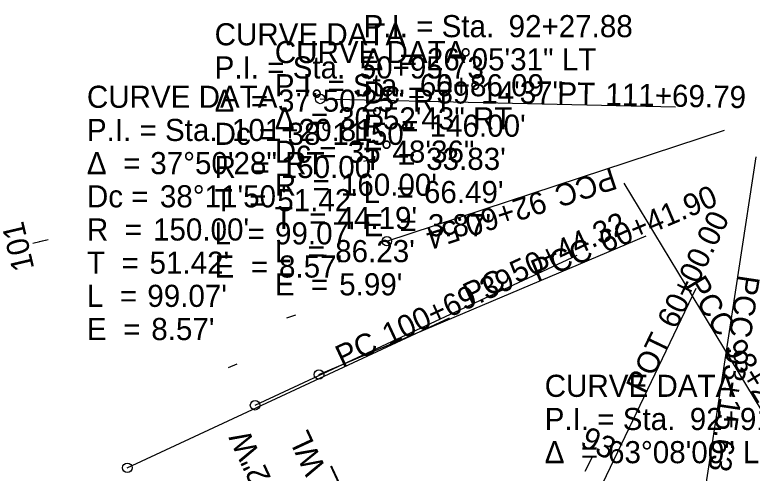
# Model space of a CAD drawing. Extents: x 1564517 to 1565226, y 635740 to 637455.
# Drawn here: x 1564729.9 to 1564823.3, y 636572.5 to 636630.6 of the extents above; entities that cross this region are included whole.
import ezdxf

# ---------------------------------------------------------------- set-up
doc = ezdxf.new("R2010")
doc.units = 0
for name, color, linetype in [('GE_P_Alignment_1000_Cardinal_Points', 7, 'Continuous'), ('GE_P_Alignment_500_Cardinal_Points', 7, 'Continuous'), ('GK_Drainage_Nodes', 7, 'Continuous'), ('SC_Scratch10', 7, 'Continuous'), ('TX_P_1000', 7, 'Continuous'), ('UT_P_Water', 7, 'Continuous'), ('UT_P_Water_Cells', 7, 'Continuous'), ('UT_X_Sanitary_Pressure_Line', 7, 'Continuous'), ('UT_X_Water_Cells', 7, 'Continuous')]:
    doc.layers.add(name, color=color, linetype=linetype)

msp = doc.modelspace()

# ---------------------------------------------------------------- linework, layer by layer
at = {"layer": 'GE_P_Alignment_1000_Cardinal_Points'}
msp.add_line((1564768.625, 636619.918), (1564813.615, 636618.935), dxfattribs=at)
msp.add_circle((1564768.625, 636619.918), 0.6, dxfattribs=at)
at = {"layer": 'GE_P_Alignment_500_Cardinal_Points'}
msp.add_line((1564768.625, 636619.918), (1564813.615, 636618.935), dxfattribs=at)
msp.add_circle((1564768.625, 636619.918), 0.6, dxfattribs=at)
at = {"layer": 'TX_P_1000'}
for p, q in [((1564768.459, 636585.03), (1564809.887, 636602.6)), ((1564760.364, 636581.139), (1564801.162, 636600.127)), ((1564796.769, 636555.382), (1564816.233, 636595.955))]:
    msp.add_line(p, q, dxfattribs=at)
at = {"layer": 'UT_P_Water_Cells'}
for p, q in [((1564777.06, 636601.911), (1564819.81, 636615.963)), ((1564817.022, 636568.096), (1564823.806, 636612.582)), ((1564830.4, 636570.761), (1564807.083, 636609.25)), ((1564734.189, 636602.095), (1564733.021, 636601.82)), ((1564768.459, 636585.03), (1564809.887, 636602.6)), ((1564760.364, 636581.139), (1564801.162, 636600.127)), ((1564796.769, 636555.382), (1564816.233, 636595.955)), ((1564744.193, 636573.226), (1564784.991, 636592.214)), ((1564802.186, 636572.809), (1564802.723, 636573.883))]:
    msp.add_line(p, q, dxfattribs=at)
for centre in [(1564777.06, 636601.911), (1564768.459, 636585.03), (1564760.364, 636581.139), (1564744.193, 636573.226)]:
    msp.add_circle(centre, 0.6, dxfattribs=at)
at = {"layer": 'UT_X_Sanitary_Pressure_Line'}
for p, q in [((1564777.06, 636601.911), (1564819.81, 636615.963)), ((1564817.022, 636568.096), (1564823.806, 636612.582)), ((1564830.4, 636570.761), (1564807.083, 636609.25)), ((1564768.459, 636585.03), (1564809.887, 636602.6)), ((1564760.364, 636581.139), (1564801.162, 636600.127)), ((1564796.769, 636555.382), (1564816.233, 636595.955)), ((1564744.193, 636573.226), (1564784.991, 636592.214))]:
    msp.add_line(p, q, dxfattribs=at)
for centre in [(1564777.06, 636601.911), (1564768.459, 636585.03), (1564760.364, 636581.139), (1564744.193, 636573.226)]:
    msp.add_circle(centre, 0.6, dxfattribs=at)
at = {"layer": 'UT_X_Water_Cells'}
for p, q in [((1564774.134, 636612.03), (1564775.298, 636612.321)), ((1564734.189, 636602.095), (1564732.242, 636601.636)), ((1564769.354, 636600.155), (1564768.16, 636600.041)), ((1564765.486, 636592.565), (1564764.359, 636592.153)), ((1564758.065, 636586.333), (1564756.959, 636585.868)), ((1564802.186, 636572.809), (1564803.081, 636574.598))]:
    msp.add_line(p, q, dxfattribs=at)

# ---------------------------------------------------------------- texts
at = {"layer": 'GE_P_Alignment_1000_Cardinal_Points'}
for s, p in [('PT', (1564798.618, 636619.263)), ('111+69.79', (1564804.703, 636619.13))]:
    msp.add_text(s, height=2.8, rotation=358.74802, dxfattribs=at).set_placement(p)
at = {"layer": 'GE_P_Alignment_500_Cardinal_Points'}
for s, p in [('PT', (1564798.618, 636619.263)), ('111+69.79', (1564804.703, 636619.13))]:
    msp.add_text(s, height=2.8, rotation=358.74802, dxfattribs=at).set_placement(p)
at = {"layer": 'GK_Drainage_Nodes'}
for s, p in [('P.I. = Sta. ', (1564774.102, 636627.735)), ('92+27.88', (1564792.47, 636627.735)), ('CURVE DATA', (1564755.248, 636626.706)), ('CURVE DATA', (1564762.868, 636624.456)), ('Δ  = ', (1564774.102, 636623.535)), ('26°05\'31" LT', (1564782.124, 636623.535)), ('P.I. = Sta. ', (1564755.248, 636622.506)), ('50+95.73', (1564773.616, 636622.506)), ('P.I. = Sta. ', (1564762.868, 636620.256)), ('60+86.09', (1564781.236, 636620.256)), ('Dc = ', (1564774.102, 636619.335)), ('39°14\'37"', (1564783.34, 636619.335)), ('CURVE DATA', (1564739.077, 636618.794)), ('Δ  = ', (1564755.248, 636618.306)), ('37°50\'25" RT', (1564763.27, 636618.306)), ('Δ  = ', (1564762.868, 636616.056)), ('30°52\'43" RT', (1564770.89, 636616.056)), ('R  = ', (1564774.102, 636615.135)), ("146.00'", (1564782.47, 636615.135)), ('P.I. = Sta. ', (1564739.077, 636614.594)), ('101+20.81', (1564757.445, 636614.594)), ('Dc = ', (1564755.248, 636614.106)), ('38°11\'50"', (1564764.486, 636614.106)), ('Dc = ', (1564762.868, 636611.856)), ('35°48\'36"', (1564772.106, 636611.856)), ('T  = ', (1564774.102, 636610.935)), ("33.83'", (1564782.034, 636610.935)), ('Δ  = ', (1564739.077, 636610.394)), ('37°50\'28" RT', (1564747.099, 636610.394)), ('R  = ', (1564755.248, 636609.906)), ("150.00'", (1564763.616, 636609.906)), ('R  = ', (1564762.868, 636607.656)), ("160.00'", (1564771.236, 636607.656)), ('L  = ', (1564774.102, 636606.735)), ("66.49'", (1564781.748, 636606.735)), ('Dc = ', (1564739.077, 636606.194)), ('38°11\'50"', (1564748.315, 636606.194)), ('T  = ', (1564755.248, 636605.706)), ("51.42'", (1564763.18, 636605.706)), ('T  = ', (1564762.868, 636603.456)), ("44.19'", (1564770.8, 636603.456)), ("150.00'", (1564747.445, 636601.994)), ('E  = ', (1564774.102, 636602.535)), ("3.87'", (1564782.254, 636602.535)), ('R  = ', (1564739.077, 636601.994)), ('L  = ', (1564755.248, 636601.506)), ("99.07'", (1564762.894, 636601.506)), ('L  = ', (1564762.868, 636599.256)), ("86.23'", (1564770.514, 636599.256)), ('T  = ', (1564739.077, 636597.794)), ("51.42'", (1564747.009, 636597.794)), ('E  = ', (1564755.248, 636597.306)), ("8.57'", (1564763.4, 636597.306)), ('E  = ', (1564762.868, 636595.056)), ("5.99'", (1564771.02, 636595.056)), ("99.07'", (1564746.723, 636593.594)), ('L  = ', (1564739.077, 636593.594)), ('E  = ', (1564739.077, 636589.394)), ("8.57'", (1564747.229, 636589.394)), ('CURVE DATA', (1564797.041, 636582.204)), ('P.I. = Sta. ', (1564797.041, 636578.004)), ('92+91.26', (1564815.409, 636578.004)), ('Δ  = ', (1564797.041, 636573.804)), ('63°08\'00" LT', (1564805.063, 636573.804))]:
    msp.add_text(s, height=2.8, dxfattribs=at).set_placement(p)
for s, p in [('CLP_WL', (1564773.341, 636564.634)), ('N24°57\'32"W', (1564768.906, 636558.046))]:
    msp.add_text(s, height=2.8, rotation=114.95884, dxfattribs=at).set_placement(p)
at = {"layer": 'SC_Scratch10'}
for s, p in [('P.I. = Sta. ', (1564774.102, 636627.735)), ('92+27.88', (1564792.47, 636627.735)), ('CURVE DATA', (1564755.248, 636626.706)), ('CURVE DATA', (1564762.868, 636624.456)), ('Δ  = ', (1564774.102, 636623.535)), ('26°05\'31" LT', (1564782.124, 636623.535)), ('P.I. = Sta. ', (1564755.248, 636622.506)), ('50+95.73', (1564773.616, 636622.506)), ('P.I. = Sta. ', (1564762.868, 636620.256)), ('60+86.09', (1564781.236, 636620.256)), ('Dc = ', (1564774.102, 636619.335)), ('39°14\'37"', (1564783.34, 636619.335)), ('CURVE DATA', (1564739.077, 636618.794)), ('Δ  = ', (1564755.248, 636618.306)), ('37°50\'25" RT', (1564763.27, 636618.306)), ('Δ  = ', (1564762.868, 636616.056)), ('30°52\'43" RT', (1564770.89, 636616.056)), ('R  = ', (1564774.102, 636615.135)), ("146.00'", (1564782.47, 636615.135)), ('P.I. = Sta. ', (1564739.077, 636614.594)), ('101+20.81', (1564757.445, 636614.594)), ('Dc = ', (1564755.248, 636614.106)), ('38°11\'50"', (1564764.486, 636614.106)), ('Dc = ', (1564762.868, 636611.856)), ('35°48\'36"', (1564772.106, 636611.856)), ('T  = ', (1564774.102, 636610.935)), ("33.83'", (1564782.034, 636610.935)), ('Δ  = ', (1564739.077, 636610.394)), ('37°50\'28" RT', (1564747.099, 636610.394)), ('R  = ', (1564755.248, 636609.906)), ("150.00'", (1564763.616, 636609.906)), ('R  = ', (1564762.868, 636607.656)), ("160.00'", (1564771.236, 636607.656)), ('L  = ', (1564774.102, 636606.735)), ("66.49'", (1564781.748, 636606.735)), ('Dc = ', (1564739.077, 636606.194)), ('38°11\'50"', (1564748.315, 636606.194)), ('T  = ', (1564755.248, 636605.706)), ("51.42'", (1564763.18, 636605.706)), ('T  = ', (1564762.868, 636603.456)), ("44.19'", (1564770.8, 636603.456)), ("150.00'", (1564747.445, 636601.994)), ('E  = ', (1564774.102, 636602.535)), ("3.87'", (1564782.254, 636602.535)), ('R  = ', (1564739.077, 636601.994)), ('L  = ', (1564755.248, 636601.506)), ("99.07'", (1564762.894, 636601.506)), ('L  = ', (1564762.868, 636599.256)), ("86.23'", (1564770.514, 636599.256)), ('T  = ', (1564739.077, 636597.794)), ("51.42'", (1564747.009, 636597.794)), ('E  = ', (1564755.248, 636597.306)), ("8.57'", (1564763.4, 636597.306)), ('E  = ', (1564762.868, 636595.056)), ("5.99'", (1564771.02, 636595.056)), ("99.07'", (1564746.723, 636593.594)), ('L  = ', (1564739.077, 636593.594)), ('E  = ', (1564739.077, 636589.394)), ("8.57'", (1564747.229, 636589.394)), ('CURVE DATA', (1564797.041, 636582.204)), ('P.I. = Sta. ', (1564797.041, 636578.004)), ('92+91.26', (1564815.409, 636578.004)), ('Δ  = ', (1564797.041, 636573.804)), ('63°08\'00" LT', (1564805.063, 636573.804))]:
    msp.add_text(s, height=2.8, dxfattribs=at).set_placement(p)
for s, p in [('CLP_WL', (1564773.341, 636564.634)), ('N24°57\'32"W', (1564768.906, 636558.046))]:
    msp.add_text(s, height=2.8, rotation=114.95884, dxfattribs=at).set_placement(p)
at = {"layer": 'UT_P_Water'}
for s, p in [('P.I. = Sta. ', (1564774.102, 636627.735)), ('92+27.88', (1564792.47, 636627.735)), ('CURVE DATA', (1564755.248, 636626.706)), ('CURVE DATA', (1564762.868, 636624.456)), ('Δ  = ', (1564774.102, 636623.535)), ('26°05\'31" LT', (1564782.124, 636623.535)), ('P.I. = Sta. ', (1564755.248, 636622.506)), ('50+95.73', (1564773.616, 636622.506)), ('P.I. = Sta. ', (1564762.868, 636620.256)), ('60+86.09', (1564781.236, 636620.256)), ('Dc = ', (1564774.102, 636619.335)), ('39°14\'37"', (1564783.34, 636619.335)), ('CURVE DATA', (1564739.077, 636618.794)), ('Δ  = ', (1564755.248, 636618.306)), ('37°50\'25" RT', (1564763.27, 636618.306)), ('Δ  = ', (1564762.868, 636616.056)), ('30°52\'43" RT', (1564770.89, 636616.056)), ('R  = ', (1564774.102, 636615.135)), ("146.00'", (1564782.47, 636615.135)), ('P.I. = Sta. ', (1564739.077, 636614.594)), ('101+20.81', (1564757.445, 636614.594)), ('Dc = ', (1564755.248, 636614.106)), ('38°11\'50"', (1564764.486, 636614.106)), ('Dc = ', (1564762.868, 636611.856)), ('35°48\'36"', (1564772.106, 636611.856)), ('T  = ', (1564774.102, 636610.935)), ("33.83'", (1564782.034, 636610.935)), ('Δ  = ', (1564739.077, 636610.394)), ('37°50\'28" RT', (1564747.099, 636610.394)), ('R  = ', (1564755.248, 636609.906)), ("150.00'", (1564763.616, 636609.906)), ('R  = ', (1564762.868, 636607.656)), ("160.00'", (1564771.236, 636607.656)), ('L  = ', (1564774.102, 636606.735)), ("66.49'", (1564781.748, 636606.735)), ('Dc = ', (1564739.077, 636606.194)), ('38°11\'50"', (1564748.315, 636606.194)), ('T  = ', (1564755.248, 636605.706)), ("51.42'", (1564763.18, 636605.706)), ('T  = ', (1564762.868, 636603.456)), ("44.19'", (1564770.8, 636603.456)), ("150.00'", (1564747.445, 636601.994)), ('E  = ', (1564774.102, 636602.535)), ("3.87'", (1564782.254, 636602.535)), ('R  = ', (1564739.077, 636601.994)), ('L  = ', (1564755.248, 636601.506)), ("99.07'", (1564762.894, 636601.506)), ('L  = ', (1564762.868, 636599.256)), ("86.23'", (1564770.514, 636599.256)), ('T  = ', (1564739.077, 636597.794)), ("51.42'", (1564747.009, 636597.794)), ('E  = ', (1564755.248, 636597.306)), ("8.57'", (1564763.4, 636597.306)), ('E  = ', (1564762.868, 636595.056)), ("5.99'", (1564771.02, 636595.056)), ("99.07'", (1564746.723, 636593.594)), ('L  = ', (1564739.077, 636593.594)), ('E  = ', (1564739.077, 636589.394)), ("8.57'", (1564747.229, 636589.394)), ('CURVE DATA', (1564797.041, 636582.204)), ('P.I. = Sta. ', (1564797.041, 636578.004)), ('92+91.26', (1564815.409, 636578.004)), ('Δ  = ', (1564797.041, 636573.804)), ('63°08\'00" LT', (1564805.063, 636573.804))]:
    msp.add_text(s, height=2.8, dxfattribs=at).set_placement(p)
for s, p in [('CLP_WL', (1564773.341, 636564.634)), ('N24°57\'32"W', (1564768.906, 636558.046))]:
    msp.add_text(s, height=2.8, rotation=114.95884, dxfattribs=at).set_placement(p)
at = {"layer": 'UT_P_Water_Cells'}
for s, rotation, p in [('PCC', 198.19555, (1564805.56, 636611.279)), ('60+41.90', 22.98217, (1564804.684, 636600.393)), ('92+60.54', 198.19555, (1564796.68, 636608.36)), ('50+44.32', 24.95884, (1564793.476, 636596.55)), ('60+00.00', 64.37239, (1564813.694, 636590.662)), ('PCC', 22.98217, (1564796.078, 636596.744)), ('100+69.39', 24.95884, (1564777.304, 636588.637)), ('PC', 24.95884, (1564787.563, 636593.798)), ('PCC', 301.20754, (1564814.855, 636596.42)), ('PCC', 261.32885, (1564821.544, 636597.753)), ('PC', 24.95884, (1564771.391, 636585.885)), ('POT', 64.37239, (1564809.745, 636582.431)), ('93+29.55', 301.20754, (1564819.699, 636588.425)), ('93+15.63', 261.32885, (1564820.135, 636588.512))]:
    msp.add_text(s, height=2.8, rotation=rotation, dxfattribs=at).set_placement(p)
at = {"layer": 'UT_X_Sanitary_Pressure_Line'}
for s, rotation, p in [('PCC', 198.19555, (1564805.56, 636611.279)), ('60+41.90', 22.98217, (1564804.684, 636600.393)), ('92+60.54', 198.19555, (1564796.68, 636608.36)), ('50+44.32', 24.95884, (1564793.476, 636596.55)), ('60+00.00', 64.37239, (1564813.694, 636590.662)), ('PCC', 22.98217, (1564796.078, 636596.744)), ('100+69.39', 24.95884, (1564777.304, 636588.637)), ('PC', 24.95884, (1564787.563, 636593.798)), ('PCC', 301.20754, (1564814.855, 636596.42)), ('PCC', 261.32885, (1564821.544, 636597.753)), ('PC', 24.95884, (1564771.391, 636585.885)), ('POT', 64.37239, (1564809.745, 636582.431)), ('93+29.55', 301.20754, (1564819.699, 636588.425)), ('93+15.63', 261.32885, (1564820.135, 636588.512))]:
    msp.add_text(s, height=2.8, rotation=rotation, dxfattribs=at).set_placement(p)
at = {"layer": 'UT_X_Water_Cells'}
for s, rotation, p in [('101', 103.26787, (1564732.424, 636598.482)), ('93', 333.41875, (1564801.379, 636576.061))]:
    msp.add_text(s, height=2.8, rotation=rotation, dxfattribs=at).set_placement(p)

doc.saveas('drawing.dxf')
